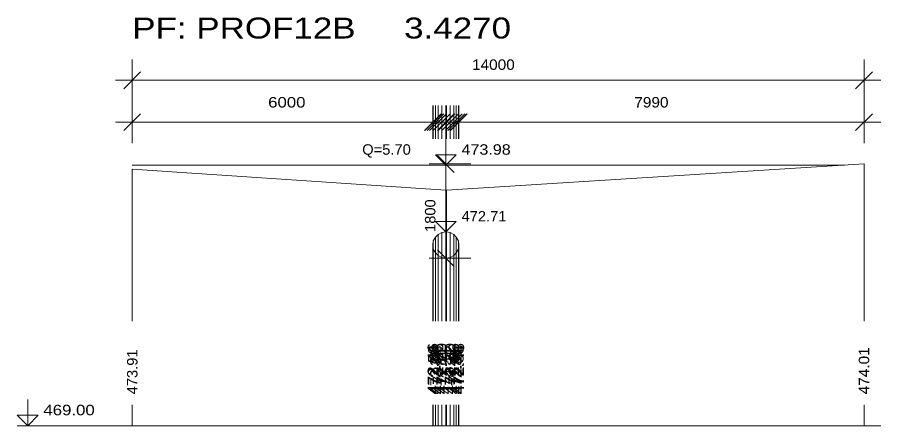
# Model space of a CAD drawing. Extents: x 7 to 442, y -393 to 441.
# Drawn here: x 293.44 to 309.95, y -282.8 to -274.99 of the extents above; entities that cross this region are included whole.
import ezdxf

# ---------------------------------------------------------------- set-up
doc = ezdxf.new("R2010")
doc.units = 0
doc.header["$LTSCALE"] = 0.08
doc.layers.add('7', color=7, linetype='Continuous', lineweight=13)

msp = doc.modelspace()

# ---------------------------------------------------------------- linework, layer by layer
at = {"layer": '7'}
for p, q in [((295.635, -277.394), (295.635, -275.794)), ((309.635, -277.394), (309.635, -275.794)), ((295.475, -276.354), (295.795, -276.034)), ((309.475, -276.354), (309.795, -276.034)), ((295.315, -276.194), (309.955, -276.194)), ((295.635, -277.314), (295.635, -276.674)), ((301.385, -277.314), (301.385, -276.674)), ((301.395, -277.314), (301.395, -276.674)), ((301.395, -277.314), (301.395, -276.674)), ((301.435, -277.314), (301.435, -276.674)), ((301.435, -277.314), (301.435, -276.674)), ((301.485, -277.314), (301.485, -276.674)), ((301.485, -277.314), (301.485, -276.674)), ((301.555, -277.314), (301.555, -276.674)), ((301.555, -277.314), (301.555, -276.674)), ((301.635, -277.314), (301.635, -276.674)), ((301.635, -277.314), (301.635, -276.674)), ((301.635, -277.314), (301.635, -276.674)), ((301.645, -277.314), (301.645, -276.674)), ((301.645, -277.314), (301.645, -276.674)), ((301.715, -277.314), (301.715, -276.674)), ((301.715, -277.314), (301.715, -276.674)), ((301.785, -277.314), (301.785, -276.674)), ((301.785, -277.314), (301.785, -276.674)), ((301.835, -277.314), (301.835, -276.674)), ((301.835, -277.314), (301.835, -276.674)), ((301.875, -277.314), (301.875, -276.674)), ((301.875, -277.314), (301.875, -276.674)), ((301.885, -277.314), (301.885, -276.674)), ((309.635, -277.314), (309.635, -276.674)), ((295.475, -277.154), (295.795, -276.834)), ((301.225, -277.154), (301.545, -276.834)), ((301.235, -277.154), (301.555, -276.834)), ((301.235, -277.154), (301.555, -276.834)), ((301.275, -277.154), (301.595, -276.834)), ((301.275, -277.154), (301.595, -276.834)), ((301.325, -277.154), (301.645, -276.834)), ((301.325, -277.154), (301.645, -276.834)), ((301.395, -277.154), (301.715, -276.834)), ((301.395, -277.154), (301.715, -276.834)), ((301.475, -277.154), (301.795, -276.834)), ((301.475, -277.154), (301.795, -276.834)), ((301.475, -277.154), (301.795, -276.834)), ((301.485, -277.154), (301.805, -276.834)), ((301.485, -277.154), (301.805, -276.834)), ((301.555, -277.154), (301.875, -276.834)), ((301.555, -277.154), (301.875, -276.834)), ((301.625, -277.154), (301.945, -276.834)), ((301.625, -277.154), (301.945, -276.834)), ((301.675, -277.154), (301.995, -276.834)), ((301.675, -277.154), (301.995, -276.834)), ((301.715, -277.154), (302.035, -276.834)), ((301.715, -277.154), (302.035, -276.834)), ((301.725, -277.154), (302.045, -276.834)), ((309.475, -277.154), (309.795, -276.834)), ((295.315, -276.994), (309.955, -276.994)), ((301.635, -279.754), (301.635, -277.474)), ((301.795, -277.954), (301.475, -277.634)), ((295.635, -277.817), (309.263, -277.817)), ((301.315, -277.794), (302.115, -277.794)), ((309.635, -280.8), (309.635, -277.794)), ((295.635, -280.8), (295.635, -277.894)), ((301.635, -280.8), (301.635, -278.294)), ((301.645, -280.8), (301.645, -278.294)), ((301.485, -280.8), (301.485, -279.144)), ((301.555, -280.8), (301.555, -279.104)), ((301.635, -280.8), (301.635, -279.094)), ((301.635, -279.094), (301.645, -279.094)), ((301.645, -280.8), (301.645, -279.094)), ((301.715, -280.8), (301.715, -279.104)), ((301.785, -280.8), (301.785, -279.144)), ((301.385, -280.8), (301.385, -279.344)), ((301.395, -280.8), (301.395, -279.264)), ((301.435, -280.8), (301.435, -279.194)), ((301.835, -280.8), (301.835, -279.194)), ((301.875, -280.8), (301.875, -279.264)), ((301.885, -280.8), (301.885, -279.344)), ((301.395, -280.8), (301.395, -279.424)), ((301.435, -280.8), (301.435, -279.494)), ((301.795, -279.754), (301.475, -279.434)), ((301.835, -280.8), (301.835, -279.494)), ((301.875, -280.8), (301.875, -279.424)), ((301.315, -279.594), (302.115, -279.594)), ((301.485, -280.8), (301.485, -279.544)), ((301.555, -280.8), (301.555, -279.584)), ((301.635, -280.8), (301.635, -279.594)), ((301.715, -280.8), (301.715, -279.584)), ((301.785, -280.8), (301.785, -279.544)), ((295.635, -282.8), (295.635, -282.4)), ((301.385, -282.8), (301.385, -282.4)), ((301.395, -282.8), (301.395, -282.4)), ((301.395, -282.8), (301.395, -282.4)), ((301.435, -282.8), (301.435, -282.4)), ((301.435, -282.8), (301.435, -282.4)), ((301.485, -282.8), (301.485, -282.4)), ((301.485, -282.8), (301.485, -282.4)), ((301.555, -282.8), (301.555, -282.4)), ((301.555, -282.8), (301.555, -282.4)), ((301.635, -282.8), (301.635, -282.4)), ((301.635, -282.8), (301.635, -282.4)), ((301.635, -282.8), (301.635, -282.4)), ((301.645, -282.8), (301.645, -282.4)), ((301.645, -282.8), (301.645, -282.4)), ((301.715, -282.8), (301.715, -282.4)), ((301.715, -282.8), (301.715, -282.4)), ((301.785, -282.8), (301.785, -282.4)), ((301.785, -282.8), (301.785, -282.4)), ((301.835, -282.8), (301.835, -282.4)), ((301.835, -282.8), (301.835, -282.4)), ((301.875, -282.8), (301.875, -282.4)), ((301.875, -282.8), (301.875, -282.4)), ((301.885, -282.8), (301.885, -282.4)), ((309.635, -282.8), (309.635, -282.4)), ((293.435, -282.8), (309.955, -282.8))]:
    msp.add_line(p, q, dxfattribs=at)
for points in [[(301.635, -277.317), (301.635, -277.817), (301.435, -277.617), (301.835, -277.617), (301.635, -277.817)], [(295.635, -277.894), (301.635, -278.294), (301.635, -279.094), (301.555, -279.104), (301.485, -279.144), (301.435, -279.194), (301.395, -279.264), (301.385, -279.344), (301.395, -279.424), (301.435, -279.494), (301.485, -279.544), (301.555, -279.584), (301.635, -279.594), (301.715, -279.584), (301.785, -279.544), (301.835, -279.494), (301.875, -279.424), (301.885, -279.344), (301.875, -279.264), (301.835, -279.194), (301.785, -279.144), (301.715, -279.104), (301.645, -279.094), (301.645, -278.294), (309.635, -277.794)], [(301.635, -278.594), (301.635, -279.094), (301.435, -278.894), (301.835, -278.894), (301.635, -279.094)], [(293.635, -282.3), (293.635, -282.8), (293.435, -282.6), (293.835, -282.6), (293.635, -282.8)]]:
    msp.add_lwpolyline(points, dxfattribs=at)

# ---------------------------------------------------------------- texts
for s, height, width, p in [('PF: PROF12B     3.4270', 0.4, 1.25, (295.635, -275.394)), ('14000', 0.2, 1.1, (302.135, -275.994)), ('6000', 0.2, 1.2, (298.235, -276.714)), ('7990', 0.2, 1.1, (305.24, -276.714)), ('Q=5.70', 0.2, 1.05, (300.035, -277.617)), ('473.98', 0.2, 1.15, (301.935, -277.617)), ('472.71', 0.2, 1.05, (301.935, -278.894)), ('469.00', 0.2, 1.2, (293.935, -282.6))]:
    msp.add_text(s, height=height, dxfattribs=dict(at, width=width)).set_placement(p)
for s, width, p in [('1800', 1.05, (301.435, -279.094)), ('472.46 ', 1.2, (301.485, -282.2)), ('472.54 ', 1.15, (301.495, -282.2)), ('472.38 ', 1.15, (301.495, -282.2)), ('472.61 ', 1.1, (301.535, -282.2)), ('472.66 ', 1.2, (301.585, -282.2)), ('472.26 ', 1.2, (301.585, -282.2)), ('472.70 ', 1.2, (301.655, -282.2)), ('472.22 ', 1.15, (301.655, -282.2)), ('472.70 ', 1.2, (301.815, -282.2)), ('472.22 ', 1.15, (301.815, -282.2)), ('472.26 ', 1.2, (301.885, -282.2)), ('472.66 ', 1.2, (301.885, -282.2)), ('472.61 ', 1.1, (301.935, -282.2)), ('472.54 ', 1.15, (301.975, -282.2)), ('472.38 ', 1.15, (301.975, -282.2)), ('472.46 ', 1.2, (301.985, -282.2)), ('474.01 ', 1.1, (309.735, -282.2)), ('473.91 ', 1.05, (295.735, -282.2)), ('472.31 ', 1.05, (301.535, -282.2)), ('473.51 ', 1.05, (301.735, -282.2)), ('472.71 ', 1.05, (301.735, -282.2)), ('472.21 ', 1.05, (301.735, -282.2)), ('472.71 ', 1.05, (301.745, -282.2)), ('473.51 ', 1.05, (301.745, -282.2)), ('472.31 ', 1.05, (301.935, -282.2))]:
    msp.add_text(s, height=0.2, rotation=90, dxfattribs=dict(at, width=width)).set_placement(p)

doc.saveas('drawing.dxf')
